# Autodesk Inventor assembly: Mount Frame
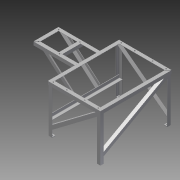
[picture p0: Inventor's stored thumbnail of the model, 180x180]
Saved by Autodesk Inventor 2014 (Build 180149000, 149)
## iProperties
Created: 2007-02
Part Number: Mount Frame
Document SubType Name: Assembly
Designer: Autodesk, Inc.
Mass: 65710.8 g
Surface Area: 27500.7 cm^2
Volume: 8360.16 cm^3
Density: 7.86 g/cm^3
Company: Autodesk, Inc.
_SolveAssemblyDoc: Frame Generator Solve Assembly
_Version: 15.0.0
Title: Frame, Mount
Author: Autodesk, Inc.
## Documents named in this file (4)
- C:\Users\iTools\Desktop\tutorial files\Tube and Pipe\Accumulator\Parts\Mount Frame.iam
- C:\Users\iTools\Desktop\tutorial files\Tube and Pipe\Accumulator\Parts\Frame Skeleton.ipt
- C:\Users\iTools\Desktop\tutorial files\Tube and Pipe\Accumulator\Parts\Frame\Accumulator Frame.iam
- C:\Users\iTools\Desktop\tutorial files\Tube and Pipe\Accumulator\Parts\Frame\Fame Foot.ipt
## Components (6 placed, 3 different names)
1. Frame Skeleton:1
2. Accumulator Frame:1 [sub-assembly] — Mate:1, Mate:2, Flush:1, Mate:3, Mate:4, Mate:5, Mate:6, Mate:7, Mate:8
3. Fame Foot:1 — Mate:1, Mate:2, Flush:1, Flush:2, Flush:3, Flush:4
4. Fame Foot:2 — Mate:5, Mate:6, Flush:3
5. Fame Foot:3 — Flush:4, Mate:7, Mate:8
6. Fame Foot:4 — Mate:3, Mate:4, Flush:2
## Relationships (12: Mate 8, Flush 4)
- Mate:1: Accumulator Frame:1 ↔ Fame Foot:1
- Mate:2: Accumulator Frame:1 ↔ Fame Foot:1
- Flush:1: Accumulator Frame:1 ↔ Fame Foot:1
- Mate:3: Accumulator Frame:1 ↔ Fame Foot:4
- Mate:4: Accumulator Frame:1 ↔ Fame Foot:4
- Flush:2: Fame Foot:1 ↔ Fame Foot:4
- Mate:5: Accumulator Frame:1 ↔ Fame Foot:2
- Mate:6: Accumulator Frame:1 ↔ Fame Foot:2
- Flush:3: Fame Foot:1 ↔ Fame Foot:2
- Flush:4: Fame Foot:1 ↔ Fame Foot:3
- Mate:7: Accumulator Frame:1 ↔ Fame Foot:3
- Mate:8: Accumulator Frame:1 ↔ Fame Foot:3
